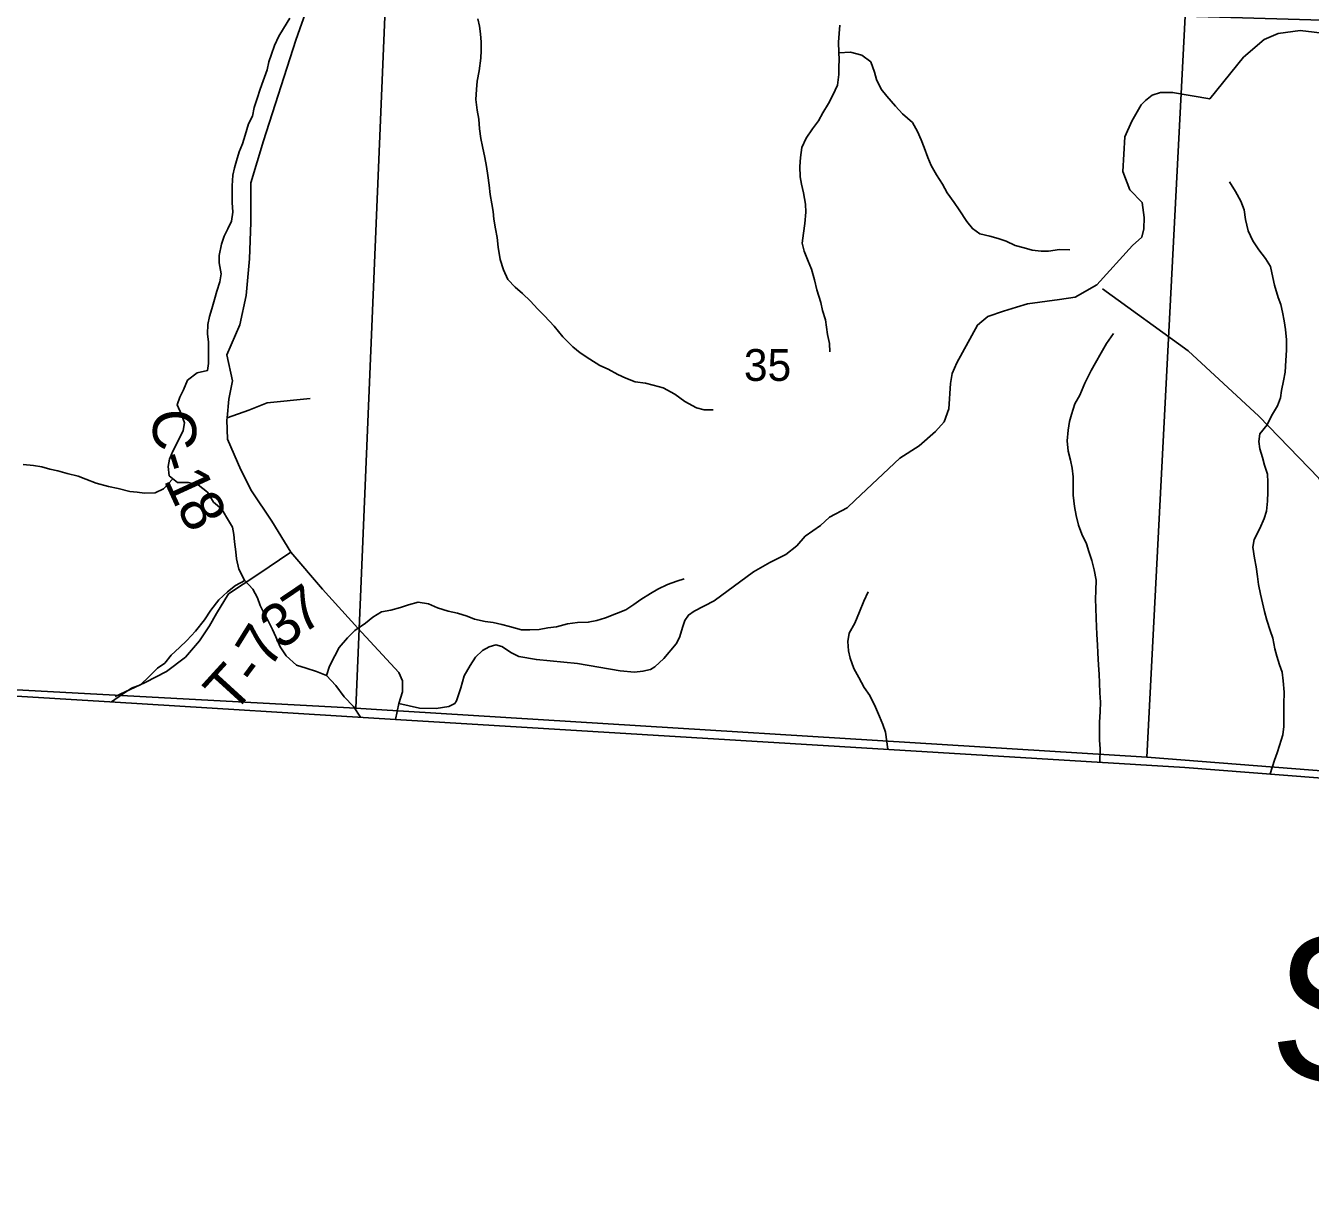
# Model space of a CAD drawing. Extents: x 1715311 to 2083412, y 146837 to 553079.
# Drawn here: x 1902515 to 1911437, y 307441 to 315575 of the extents above; entities that cross this region are included whole.
import ezdxf

# ---------------------------------------------------------------- set-up
doc = ezdxf.new("R2010")
doc.units = 0
for name, color, linetype in [('GM_X_Adjacent_County', 7, 'Continuous'), ('GM_X_Adjacent_County_Text', 7, 'Continuous'), ('GM_X_County', 7, 'Continuous'), ('GM_X_County_Road', 7, 'Continuous'), ('GM_X_County_Road_Text', 7, 'Continuous'), ('GM_X_Minor_River', 7, 'Continuous'), ('GM_X_Section', 7, 'Continuous'), ('GM_X_Section_Text', 7, 'Continuous'), ('GM_X_Township', 7, 'Continuous'), ('GM_X_Township_Road', 7, 'Continuous'), ('GM_X_Township_Road_Text', 7, 'Continuous'), ('GM_X_Township_ROW', 7, 'Continuous')]:
    doc.layers.add(name, color=color, linetype=linetype)

msp = doc.modelspace()

# ---------------------------------------------------------------- linework, layer by layer
at = {"layer": 'GM_X_Adjacent_County'}
msp.add_lwpolyline([(1896008.1, 339457.6), (1895778.9, 336658.8), (1895744.3, 336194.3), (1895698.9, 335683.3), (1895662.8, 335243.7), (1895522.9, 333111.5), (1895187.9, 327844.5), (1894918.6, 323647.3), (1894855.8, 322668.3), (1894262.9, 318799.6), (1893959.5, 316893.5), (1894018.6, 315798.2), (1894251.9, 311474.1), (1895507.9, 311379), (1897304.4, 311233.1), (1901800, 310959.2), (1903135.1, 310877.8), (1905084.1, 310759.1), (1910566.5, 310425.2), (1912652.3, 310262.4)], dxfattribs=at)
at = {"layer": 'GM_X_County'}
msp.add_lwpolyline([(1912652.3, 310262.4), (1910566.5, 310425.2), (1905084.1, 310759.1), (1903135.1, 310877.8), (1901800, 310959.2), (1897304.4, 311233.1), (1895507.9, 311379), (1894251.9, 311474.1), (1894018.6, 315798.2), (1893959.5, 316893.5), (1894262.9, 318799.6), (1894855.8, 322668.3), (1894918.6, 323647.3), (1895187.9, 327844.5), (1895522.9, 333111.5), (1895662.8, 335243.7), (1895698.9, 335683.3), (1895744.3, 336194.3), (1895778.9, 336658.8), (1896008.1, 339457.6)], dxfattribs=at)
at = {"layer": 'GM_X_County_Road'}
msp.add_lwpolyline([(1905084.1, 310759.1), (1905106.2, 310868.3), (1905131.2, 310951.1), (1905132.7, 311026), (1905106.2, 311085.3), (1904821.9, 311392.9), (1904576.2, 311663.5), (1904356.2, 311920.1), (1904224.8, 312134.5), (1904083, 312346.9), (1904009.2, 312491.2), (1903915.4, 312703.6), (1903911.5, 312837.9), (1903913, 312852.8), (1903925.7, 312982.1), (1903951.9, 313110.3), (1903912.1, 313290.6), (1904002.3, 313498.9), (1904046.6, 313703.2), (1904068.8, 313957.6), (1904079.1, 314208), (1904077.5, 314484.5), (1904165.8, 314776.9), (1904390.6, 315473.9), (1904472.8, 315704.2)], dxfattribs=at)
at = {"layer": 'GM_X_Minor_River'}
for points in [[(1904350.5, 315628), (1904306.3, 315556), (1904274.1, 315502.1), (1904243.9, 315438.1), (1904221.8, 315378.1), (1904203.6, 315324.1), (1904191.5, 315270), (1904163.2, 315192), (1904143.1, 315134), (1904122.9, 315070), (1904102.7, 315008), (1904090.5, 314948), (1904062.4, 314894), (1904040.2, 314816), (1904020, 314756), (1903997.8, 314700), (1903979.7, 314638), (1903965.5, 314588), (1903953.4, 314537.9), (1903949.1, 314463.8), (1903948.8, 314347.7), (1903954.6, 314279.6), (1903944.4, 314217.6), (1903918.2, 314165.6), (1903894.1, 314113.6), (1903873.9, 314059.6), (1903859.7, 313979.6), (1903859.5, 313929.5), (1903873.3, 313851.4), (1903863.1, 313797.3), (1903842.9, 313731.3), (1903826.8, 313673.3), (1903806.6, 313609.3), (1903792.4, 313555.3), (1903780.3, 313501.2), (1903778.1, 313435.2), (1903783.9, 313377.1), (1903785.6, 313303), (1903785.4, 313230.9), (1903777.3, 313180.9), (1903705.3, 313165.1), (1903639.2, 313113.2), (1903611, 313047.2), (1903584.8, 312995.3), (1903566.7, 312943.3), (1903596.5, 312875.1), (1903618.3, 312819), (1903608.1, 312764.9), (1903573.9, 312693), (1903535.7, 312621), (1903513.5, 312565), (1903505.4, 312515), (1903511.2, 312450.9), (1903569, 312404.6), (1903645, 312404.4), (1903712.9, 312388.2), (1903776.6, 312335.9), (1903818.4, 312267.7), (1903876.2, 312217.5), (1903910, 312163.3), (1903951.8, 312093.1), (1903961.6, 312043), (1903965.4, 311991), (1903973.2, 311922.9), (1903979.1, 311872.8), (1903994.8, 311802.7)], [(1905655.5, 315622.1), (1905667.3, 315572), (1905673.2, 315517.9), (1905679, 315461.8), (1905678.8, 315403.7), (1905676.6, 315349.7), (1905664.4, 315261.6), (1905650.2, 315189.6), (1905646, 315131.5), (1905641.8, 315063.5), (1905651.5, 314989.3), (1905661.3, 314927.2), (1905667.1, 314859.1), (1905674.9, 314791), (1905686.7, 314737), (1905704.5, 314660.8), (1905714.3, 314596.7), (1905724.1, 314534.6), (1905733.9, 314468.5), (1905741.7, 314404.4), (1905753.4, 314338.3), (1905761.3, 314286.2), (1905767.1, 314232.1), (1905778.9, 314164), (1905788.7, 314103.9), (1905796.5, 314037.8), (1905810.2, 313951.7), (1905834, 313879.5), (1905863.7, 313813.3), (1905913.5, 313759.1), (1905965.4, 313714.9), (1906021.2, 313662.7), (1906069, 313610.5), (1906118.8, 313560.3), (1906184.5, 313490), (1906246.2, 313415.7), (1906314, 313345.5), (1906365.8, 313303.3), (1906433.6, 313259), (1906503.4, 313216.8), (1906559.3, 313190.5), (1906627.1, 313154.3), (1906683, 313128.1), (1906748.9, 313101.9), (1906818.8, 313093.7), (1906872.7, 313079.5), (1906942.6, 313061.2), (1907022.4, 313017), (1907092.2, 312966.7), (1907174, 312922.4), (1907227.9, 312908.2), (1907289.9, 312908)], [(1908169.5, 315578.5), (1908165.4, 315520.4), (1908159.2, 315460.3), (1908163, 315390.3), (1908164.8, 315340.2), (1908162.6, 315288.1), (1908162.5, 315236.1), (1908152.3, 315162), (1908120.1, 315094.1), (1908089.9, 315034.1), (1908051.7, 314970.1), (1908021.6, 314914.1), (1907979.5, 314860.2), (1907935.3, 314794.3), (1907905.1, 314730.3), (1907896.9, 314660.2), (1907892.7, 314598.2), (1907894.5, 314526.1), (1907902.3, 314474), (1907918.1, 314413.9), (1907931.9, 314335.7), (1907933.7, 314281.7), (1907925.5, 314201.6), (1907917.3, 314135.6), (1907909, 314065.5), (1907922.9, 314009.4), (1907950.6, 313941.2), (1907972.4, 313885.1), (1907994.2, 313811), (1908010, 313740.8), (1908037.7, 313654.6), (1908049.5, 313598.5), (1908069.3, 313532.4), (1908077.1, 313482.3), (1908084.9, 313430.2), (1908096.7, 313368.1), (1908100.6, 313310.1)], [(1908163.1, 315387.6), (1908242.9, 315392), (1908322.8, 315371.8), (1908384.6, 315323.5), (1908410.4, 315253.4), (1908424.2, 315201.3), (1908456, 315135.1), (1908495.8, 315084.9), (1908555.5, 315016.7), (1908605.3, 314962.5), (1908673.1, 314904.2), (1908708.9, 314840), (1908734.7, 314783.9), (1908754.5, 314729.7), (1908780.2, 314659.6), (1908804.1, 314605.5), (1908841.8, 314539.3), (1908883.6, 314475.1), (1908915.4, 314414.9), (1908963.2, 314348.7), (1908999, 314296.5), (1909050.7, 314216.3), (1909090.5, 314166.1), (1909142.3, 314129.9), (1909210.2, 314113.7), (1909270.2, 314097.5), (1909324.1, 314079.3), (1909387.9, 314049.1), (1909449.8, 314032.9), (1909505.7, 314016.7), (1909567.7, 314010.5), (1909619.6, 314010.3), (1909695.6, 314022.1), (1909767.6, 314019.9)], [(1911159.4, 310379.8), (1911187.5, 310475.7), (1911207.6, 310527.7), (1911223.8, 310577.8), (1911246, 310651.8), (1911254.2, 310709.8), (1911254.4, 310791.9), (1911252.7, 310864), (1911254.9, 310948.1), (1911249.2, 311026.2), (1911241.4, 311086.3), (1911223.5, 311138.4), (1911203.7, 311198.5), (1911191.9, 311248.6), (1911176.1, 311322.7), (1911158.3, 311376.8), (1911134.6, 311447), (1911118.8, 311507.1), (1911105, 311569.2), (1911091.2, 311629.3), (1911077.4, 311695.4), (1911069.5, 311751.5), (1911061.8, 311817.6), (1911050, 311877.7), (1911038.2, 311953.8), (1911048.4, 312007.9), (1911086.6, 312083.8), (1911116.8, 312153.8), (1911132.9, 312203.8), (1911139.1, 312273.9), (1911141.3, 312336), (1911141.5, 312406), (1911139.7, 312462.1), (1911119.9, 312524.2), (1911104.1, 312576.3), (1911086.3, 312636.5), (1911080.5, 312688.5), (1911086.6, 312740.6), (1911136.8, 312804.5), (1911166.9, 312866.5), (1911209.1, 312936.5), (1911229.3, 312992.5), (1911237.4, 313042.5), (1911251.6, 313110.5), (1911261.8, 313168.6), (1911268.1, 313250.6), (1911272.3, 313322.7), (1911272.5, 313394.8), (1911264.7, 313464.9), (1911254.9, 313527), (1911245.1, 313587.1), (1911233.3, 313639.2), (1911213.5, 313689.3), (1911187.7, 313773.5), (1911175.9, 313827.6), (1911160.2, 313903.7), (1911126.4, 313957.8), (1911080.6, 314020.1), (1911038.8, 314082.2), (1911005.1, 314150.4), (1910987.3, 314228.6), (1910977.5, 314296.7), (1910955.7, 314356.8), (1910918, 314425), (1910876.2, 314491.2)], [(1909976.1, 310462), (1909976.6, 310555.4), (1909972.8, 310615.5), (1909973.2, 310737.6), (1909977.4, 310813.7), (1909979.6, 310877.7), (1909975.8, 310943.8), (1909972.1, 311011.9), (1909970.3, 311074), (1909966.4, 311136), (1909960.7, 311220.2), (1909958.9, 311276.2), (1909955.1, 311348.3), (1909951.3, 311404.4), (1909949.5, 311460.5), (1909947.7, 311534.6), (1909945.9, 311594.6), (1909948.1, 311652.7), (1909950.3, 311724.8), (1909936.5, 311796.9), (1909918.7, 311861), (1909898.9, 311925.1), (1909883.1, 311977.2), (1909849.4, 312045.4), (1909827.6, 312107.6), (1909811.8, 312173.7), (1909800, 312237.8), (1909790.2, 312315.9), (1909790.5, 312394), (1909790.6, 312444.1), (1909782.8, 312504.1), (1909771, 312558.2), (1909755.2, 312622.4), (1909749.4, 312692.5), (1909755.7, 312766.5), (1909765.8, 312826.6), (1909778, 312876.6), (1909802.2, 312950.6), (1909836.4, 313010.6), (1909870.6, 313092.5), (1909914.8, 313180.5), (1909945, 313234.5), (1909985.2, 313304.5), (1910021.3, 313368.4), (1910069.5, 313438.4)], [(1903537.5, 312429.8), (1903470.9, 312358.9), (1903414.9, 312333), (1903340.9, 312329.2), (1903289, 312337.4), (1903237.1, 312341.6), (1903157.2, 312361.8), (1903089.3, 312376), (1903005.4, 312398.3), (1902933.5, 312426.6), (1902879.6, 312448.8), (1902801.8, 312467), (1902737.9, 312485.2), (1902681.9, 312497.4), (1902626, 312511.6), (1902568.1, 312521.8), (1902498.2, 312528)], [(1903994.8, 311802.7), (1904034.6, 311724.5), (1904092.3, 311662.2), (1904124.1, 311602), (1904143.9, 311549.9), (1904167.8, 311499.8), (1904199.6, 311443.6), (1904229.4, 311383.5), (1904253.2, 311333.3), (1904283, 311263.2), (1904324.7, 311201), (1904396.5, 311134.7), (1904462.4, 311114.5), (1904534.2, 311092.2), (1904604.1, 311064), (1904669.8, 310993.7), (1904727.6, 310915.5), (1904791.3, 310849.2), (1904839.9, 310774.8)], [(1904036, 311723), (1903972.5, 311688.6), (1903916.4, 311644.7), (1903856.3, 311588.8), (1903800.1, 311516.9), (1903755.9, 311451), (1903693.7, 311371.1), (1903633.6, 311307.2), (1903583.4, 311257.3), (1903525.3, 311205.4), (1903481.2, 311149.5), (1903431.1, 311113.6), (1903373, 311057.7), (1903312.8, 310999.8), (1903248.8, 310976), (1903186.7, 310934.1), (1903110.4, 310880.2)], [(1904604.1, 311064), (1904624.3, 311128), (1904662.5, 311200), (1904692.6, 311257.9), (1904748.8, 311325.8), (1904800.9, 311375.8), (1904875, 311427.6), (1904925.1, 311469.5), (1904985.2, 311505.3), (1905051.2, 311517.2), (1905119.2, 311535), (1905173.2, 311554.8), (1905241.2, 311572.6), (1905313.1, 311562.4), (1905375, 311534.2), (1905448.9, 311510), (1905514.8, 311495.7), (1905580.7, 311475.5), (1905632.6, 311455.3), (1905706.5, 311439.1), (1905762.4, 311430.9), (1905822.3, 311418.7), (1905876.2, 311404.6), (1905958.1, 311380.3), (1906016.1, 311380.1), (1906082, 311383.9), (1906142, 311393.8), (1906202, 311401.6), (1906278, 311423.4), (1906348, 311431.2), (1906421.9, 311433), (1906481.9, 311444.8), (1906542, 311464.6), (1906618, 311494.4), (1906682, 311520.3), (1906738.1, 311556.1), (1906788.2, 311592), (1906854.2, 311633.9), (1906904.3, 311663.8), (1906972.4, 311695.6), (1907038.4, 311719.4), (1907088.4, 311735.3)], [(1908503.3, 310551.6), (1908486.1, 310669.9), (1908468.3, 310724), (1908444.4, 310778.2), (1908416.7, 310844.3), (1908376.9, 310924.5), (1908339.1, 310980.7), (1908301.4, 311048.9), (1908265.6, 311113.1), (1908241.8, 311183.2), (1908230, 311235.3), (1908226.2, 311299.4), (1908234.4, 311357.5), (1908274.6, 311427.4), (1908306.8, 311505.4), (1908337, 311579.4), (1908367.2, 311645.4)]]:
    msp.add_lwpolyline(points, dxfattribs=at)
at = {"layer": 'GM_X_Section'}
for points in [[(1899470.3, 316692.5), (1905031.9, 316191.2), (1904807.1, 310835.9), (1899450.6, 311126.2), (1899255.1, 311137.1)], [(1905031.9, 316191.2), (1910567.5, 315641.9), (1910301, 310496.7), (1904914.8, 310829.3), (1904807.1, 310835.9)], [(1910567.5, 315641.9), (1915889.8, 315487.1), (1915474.6, 310091.9), (1910301, 310496.7)]]:
    msp.add_lwpolyline(points, close=True, dxfattribs=at)
at = {"layer": 'GM_X_Township'}
msp.add_lwpolyline([(1912652.3, 310262.4), (1910566.5, 310425.2), (1905084.1, 310759.1), (1903135.1, 310877.8), (1901800, 310959.2), (1897304.4, 311233.1), (1895507.9, 311379), (1894251.9, 311474.1), (1894018.6, 315798.2), (1893959.5, 316893.5), (1894262.9, 318799.6), (1894855.8, 322668.3), (1894918.6, 323647.3), (1895187.9, 327844.5), (1895522.9, 333111.5), (1895662.8, 335243.7), (1895698.9, 335683.3), (1895744.3, 336194.3), (1895778.9, 336658.8), (1896008.1, 339457.6)], dxfattribs=at)
at = {"layer": 'GM_X_Township_Road'}
for points in [[(1903913, 312852.8), (1904065.6, 312905.9), (1904191.7, 312957.9), (1904490.6, 312986)], [(1903136.1, 310917.1), (1903345.5, 311015.3), (1903493.6, 311091.3), (1903623.7, 311191.4), (1903721.8, 311303.5), (1903791.9, 311409.6), (1903840, 311493.7), (1903924.2, 311629.9), (1904128.3, 311766), (1904356.2, 311920.1)]]:
    msp.add_lwpolyline(points, dxfattribs=at)
at = {"layer": 'GM_X_Township_ROW'}
for points in [[(1909694.7, 313674.5), (1909803.5, 313689.4), (1909954.5, 313775.4), (1910202.4, 314048.5), (1910266.3, 314108.2), (1910281.4, 314164.1), (1910283.5, 314243.7), (1910268.5, 314347), (1910182.8, 314436), (1910135.6, 314563.5), (1910149.8, 314802.8), (1910197, 314911.5), (1910261.5, 315024.8), (1910293, 315056.3), (1910338.9, 315092.4), (1910396.9, 315111.4), (1910480.1, 315112.2), (1910738.8, 315067), (1910972.3, 315356.1), (1911117.8, 315478.9), (1911214.8, 315522.3), (1911366.5, 315542.7), (1911715.4, 315500.8)], [(1909992.8, 313747.7), (1910588.5, 313317.4), (1911078.9, 312863.7), (1911495.8, 312434.6), (1912047.4, 311686.7), (1912329.4, 311208.6), (1912599.1, 310656.9), (1912652.3, 310262.4)], [(1909156, 313521.1), (1909198.4, 313556.1), (1909306.8, 313594.4), (1909395.6, 313620.9), (1909472.6, 313644), (1909694.7, 313674.5)], [(1905106.2, 310868.3), (1905249.7, 310837.1), (1905365.2, 310835.5), (1905454.1, 310849.6), (1905494.7, 310868.3), (1905507.2, 310887), (1905536.8, 310979.1), (1905560.2, 311060.3), (1905602.3, 311133.7), (1905639.8, 311191.4), (1905688.2, 311238.2), (1905733.4, 311263.2), (1905780.2, 311275.7), (1905822.3, 311264.7), (1905887.9, 311221.1), (1905940.9, 311196.1), (1906062.6, 311174.2), (1906348.1, 311146.1), (1906643.4, 311096.8), (1906743.9, 311085.9), (1906802.3, 311092.7), (1906853.9, 311105), (1906885.1, 311124), (1906947.6, 311182.4), (1907033.2, 311282.9), (1907056.3, 311326.4), (1907078, 311403.8), (1907092.9, 311445.9), (1907117.4, 311482.6), (1907158.1, 311511.2), (1907296.4, 311583), (1907570, 311784), (1907683.5, 311847.3), (1907795.2, 311903.2), (1907869.7, 311964.6), (1907929.2, 312031.7), (1908035.3, 312106.2), (1908098.4, 312163.6), (1908221.4, 312228.3), (1908276.6, 312280.3), (1908587.3, 312572.2), (1908721.2, 312658.4), (1908834.9, 312756.8), (1908894.8, 312824.6), (1908926.4, 312914.5), (1908938.9, 313091.7), (1908949.1, 313161.2), (1908981.9, 313235.2), (1909125.8, 313496.2), (1909156, 313521.1)]]:
    msp.add_lwpolyline(points, dxfattribs=at)

# ---------------------------------------------------------------- texts
at = {"layer": 'GM_X_Adjacent_County_Text'}
msp.add_text('SCIOTO COUNTY', height=1000, rotation=355.50493, dxfattribs=at).set_placement((1911133.2, 308284))
at = {"layer": 'GM_X_County_Road_Text'}
for s, rotation, p in [('C', 272.78777, (1903391.5, 312906.9)), ('-', 287.39828, (1903418.1, 312578.7)), ('1', 294.62308, (1903469.8, 312422.6)), ('8', 298.31547, (1903556.2, 312235.8))]:
    msp.add_text(s, height=300, rotation=rotation, dxfattribs=at).set_placement(p)
at = {"layer": 'GM_X_Section_Text'}
msp.add_text('35', height=221, rotation=0.00001, dxfattribs=at).set_placement((1907503.1, 313109.1))
at = {"layer": 'GM_X_Township_Road_Text'}
for s, rotation, p in [('7', 34.02531, (1904430.4, 311341.6)), ('3', 37.17263, (1904287.9, 311233.4)), ('7', 58.18658, (1904210.7, 311099)), ('T', 47.64346, (1903950.9, 310787.4)), ('-', 53.47348, (1904122.9, 310978.6))]:
    msp.add_text(s, height=300, rotation=rotation, dxfattribs=at).set_placement(p)

doc.saveas('drawing.dxf')
